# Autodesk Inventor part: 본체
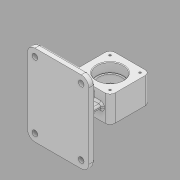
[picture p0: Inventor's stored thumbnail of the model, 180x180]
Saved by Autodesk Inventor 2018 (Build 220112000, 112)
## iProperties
Created: 2020-11
Part Number: 본체
Material: 일반
Document SubType Name: Modeling
Designer: 1-16
Density: 1 g/cm^3
Appearance: 기본값
Mass: 253.042 g
Surface Area: 542.794 cm^2
Volume: 253.042 cm^3
Author: 1-16
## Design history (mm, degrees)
sketch "스케치2"
  geometry: L1 (0, 0)-(64, 0); L2 (64, 0)-(64, 64); L3 (64, 64)-(0, 64); L4 (0, 64)-(0, 0)
  constraints: 8 end point, 2 parallel, 1 horizontal, 1 perpendicular
  dimensions: "d0" = 64 distance of L2.end L3.end; "d1" = 64 distance of L1.end L2.end
extrude "돌출1" new body sketch "스케치2" distance "d2" = 42; taper "d3" = 0 deg
sketch "스케치3"
  geometry: L1 (0, 64)-(64, 64) reference; L2 (64, 0)-(0, 0) reference; L3 (64, 64)-(64, 0) reference; C1 r 21 at (32, 32); 2 further points
  constraints: 2 midpoint, 1 centre point, 1 horizontal alignment, 1 vertical alignment
  dimensions: "d4" = 42 diameter of C1
extrude "돌출2" cut sketch "스케치3" distance "d5" = 15; taper "d6" = 0 deg
node "작업 평면1"
sketch "스케치4"
  geometry: L1 (32, -32)-(32, 32) reference; L2 (32, 32)-(-32, 32) reference; C1 r 18 at (0, 0); 2 further points
  constraints: 2 midpoint, 1 centre point, 1 horizontal alignment, 1 vertical alignment
  dimensions: "d7" = 36 diameter of C1
extrude "돌출3" cut sketch "스케치4" extent not by distance; stored distance "d8" = 0; taper "d9" = 0 deg
fillet "모깎기1" dims "d10" = 8
hole "구멍1" diameter "d13" = 3.242; stored, may be unused: countersink angle "d17" = 90 deg, drill point angle "d19" = 118 deg; dims "d11" = 10, "d12" = 10, "d14" = 8, "d15" = 4, "d16" = 2, "d18" = 10
node "작업 평면2"
node "작업 평면3"
node "작업 평면4"
sketch "스케치6"
  geometry: L1 (-38, -44)-(60, -44); L2 (60, -44)-(60, 86); L3 (60, 86)-(-38, 86); L4 (-38, 86)-(-38, -44); L5 (-38, -44)-(60, 86); L6 (60, -44)-(-38, 86); L7 (-8, 42)-(-8, 0) reference; L8 (0, 0)-(0, 42) reference; L9 (48, 0)-(0, 0) reference; L10 (48, 42)-(48, 0) reference; L11 (0, 42)-(48, 42) reference; 3 further points
  constraints: 12 end point, 4 midpoint, 2 parallel, 1 horizontal, 1 horizontal alignment, 1 perpendicular
  dimensions: "d25" = 130 distance of L1.end L2.end; "d26" = 98 distance of L2.end L3.end; "d27" = 30 distance between parallel lines of L7 L4
extrude "돌출4" join sketch "스케치6" distance "d28" = 10; taper "d29" = 0 deg
sketch "스케치8"
  geometry: L1 (44, 17)-(4, 17); L2 (4, 17)-(4, 25); L3 (4, 25)-(44, 25); L4 (44, 25)-(44, 17); L5 (44, 17)-(4, 25); L6 (4, 17)-(44, 25); L7 (-38, 86)-(-38, -44) reference; 4 further points
  constraints: 12 end point, 4 midpoint, 2 parallel, 1 horizontal, 1 horizontal alignment, 1 perpendicular
  dimensions: "d30" = 40 distance between parallel lines of L4 L2; "d32" = 8 distance between parallel lines of L1 L3; "d37" = 62 distance from line of L7 point (24, 21)
extrude "돌출5" join sketch "스케치8" stored distance "d33" = 10; taper "d34" = 0 deg
sketch "스케치9"
  geometry: L1 (20, 4)-(28, 4); L2 (28, 4)-(28, 38); L3 (28, 38)-(20, 38); L4 (20, 38)-(20, 4); L5 (20, 4)-(28, 38); L6 (28, 4)-(20, 38); L7 (60, 86)-(-38, 86) reference; L8 (-38, 86)-(-38, -44) reference; 2 further points
  constraints: 12 end point, 2 midpoint, 2 parallel, 1 horizontal, 1 perpendicular
  dimensions: "d35" = 34 distance between parallel lines of L3 L1; "d36" = 8 distance between parallel lines of L2 L4; "d38" = 65 distance from line of L7 point (24, 21); "d39" = 62 distance from line of L8 point (24, 21)
extrude "돌출6" join sketch "스케치9" stored distance "d40" = 10; taper "d41" = 0 deg
fillet "모깎기2" dims "d42" = 12
hole "구멍2" diameter "d45" = 9; stored, may be unused: countersink angle "d49" = 90 deg, drill point angle "d51" = 118 deg; dims "d43" = 10, "d44" = 10, "d46" = 8, "d47" = 4, "d48" = 2, "d50" = 10
node "작업 평면5"
node "작업 평면6"
fillet "모깎기3" dims "d52" = 3
fillet "모깎기4" dims "d53" = 3
chamfer "모따기1" distance "d54" = 1; stored, may be unused: second distance "d55" = 2, angle "d56" = 45 deg
fillet "모깎기5" dims "d57" = 0.3
sketch "스케치10"
  geometry: L1 (-38, 74)-(-38, -32) reference; L2 (48, 86)-(-26, 86) reference; 2 further points
  constraints: 1 other
  dimensions: "d58" = 10 distance from line of L1 point (-28, 21); "d59" = 65 distance from line of L2 point (-28, 21)
feature "엠보싱1" sketch "스케치10" dims "d0" = 64, "d1" = 64, "d60" = 0.5, "d61" = 0
node "솔리드1"
mirror "미러1"
mirror "미러2"
mirror "미러3"
mirror "미러4"
mirror "미러5"
mirror "미러6"
node "투영된 루프1"
